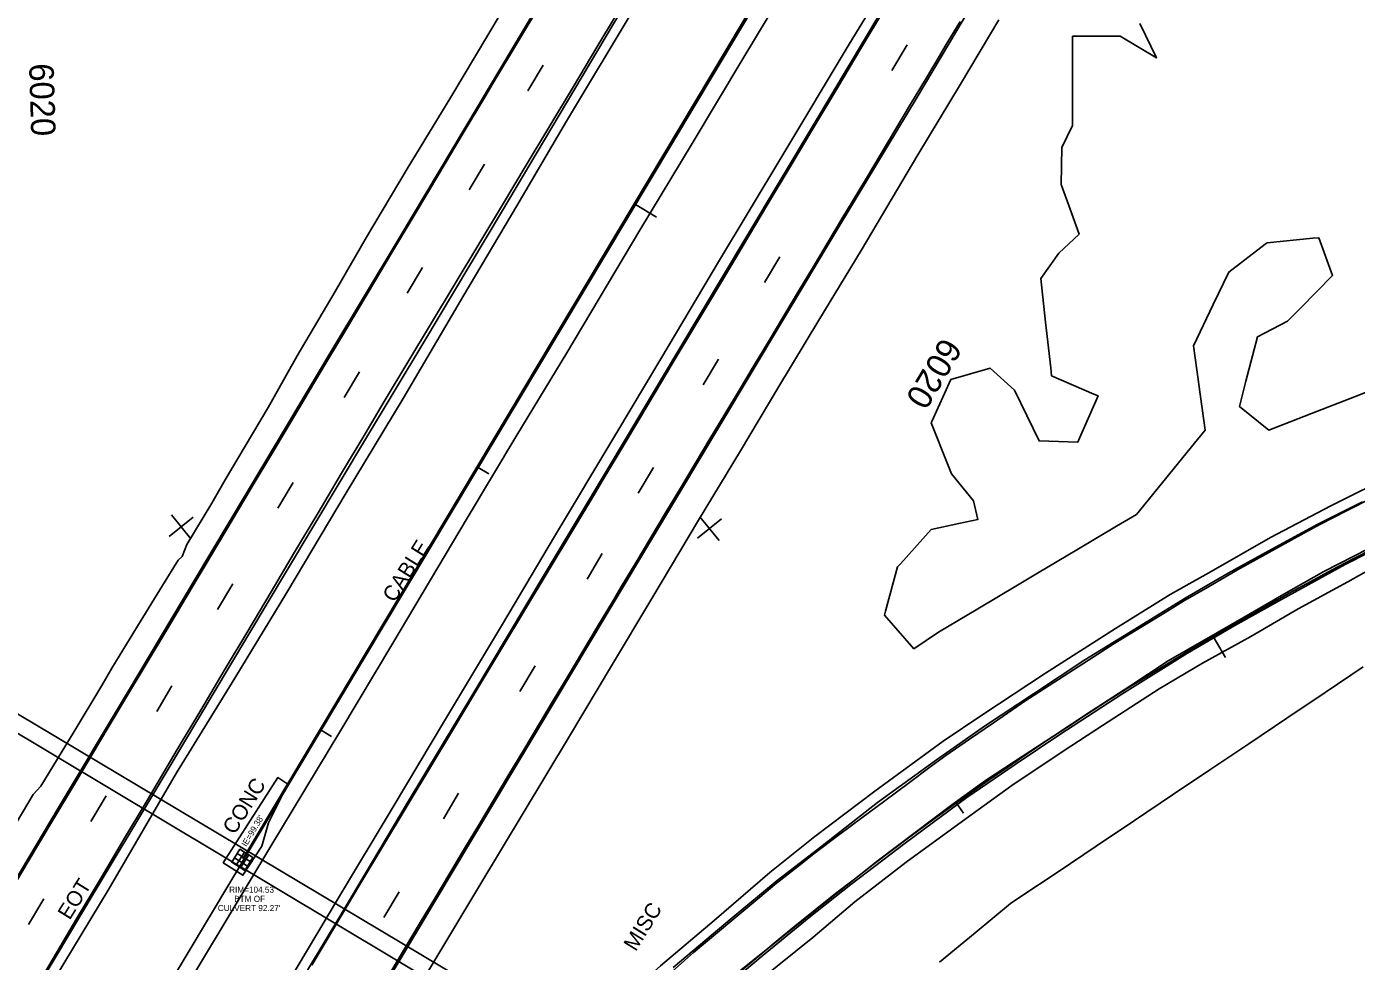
# Model space of a CAD drawing. Extents: x 2132221 to 2141942, y 535736 to 547298.
# Drawn here: x 2137298 to 2137732.2, y 539432.5 to 539737.8 of the extents above; entities that cross this region are included whole.
import ezdxf

# ---------------------------------------------------------------- set-up
doc = ezdxf.new("R2010")
doc.units = 0
for name, color, linetype in [('RD_EX_Conc', 7, 'Continuous'), ('RD_EX_Conc_txCode', 7, 'Continuous'), ('RD_EX_DR_Inlet', 7, 'Continuous'), ('RD_EX_DR_Inlet_txCode', 7, 'Continuous'), ('RD_EX_DR_Pipe', 7, 'Continuous'), ('RD_EX_GuardRail', 7, 'Continuous'), ('RD_EX_GuardRail_txCode', 7, 'Continuous'), ('RD_EX_Misc', 7, 'Continuous'), ('RD_EX_Misc_txCode', 7, 'Continuous'), ('RD_EX_Road', 7, 'Continuous'), ('RD_EX_VEG', 7, 'Continuous'), ('RD_HC_Cl', 7, 'Continuous'), ('RD_HC_Data_Tic', 7, 'Continuous'), ('RD_HC_TX_Sta50', 7, 'Continuous')]:
    doc.layers.add(name, color=color, linetype=linetype)

msp = doc.modelspace()

# ---------------------------------------------------------------- linework, layer by layer
at = {"layer": 'RD_EX_Conc'}
for p, q in [((2137527.69, 539374.58), (2137173.5, 539585.79)), ((2137170.3, 539581.57), (2137523.27, 539370.49))]:
    msp.add_line(p, q, dxfattribs=at)
for points in [[(2137242.23, 539372.03), (2137263.99, 539408.38), (2137286.63, 539446.29), (2137308.35, 539482.58), (2137330.9, 539520.32), (2137352.84, 539557.03), (2137375.41, 539594.83), (2137397.01, 539631.04), (2137419.62, 539668.7), (2137441.46, 539705.12), (2137463.96, 539742.92), (2137485.77, 539779.43), (2137508.5, 539817.41), (2137530.04, 539853.47), (2137547.89, 539883.34), (2137565.16, 539912.21), (2137584.16, 539944.01), (2137609.52, 539986.34), (2137628.42, 540017.94)], [(2137263.04, 539359.5), (2137275.58, 539380.34), (2137294.64, 539412.29), (2137320.12, 539454.95), (2137338.88, 539486.39), (2137364.26, 539528.76), (2137383.24, 539560.45), (2137408.68, 539602.98), (2137427.67, 539634.75), (2137453.05, 539677.2), (2137471.87, 539708.82), (2137497.19, 539751.42), (2137516.41, 539783.43), (2137541.62, 539825.46), (2137561.12, 539858.06), (2137585.95, 539899.61), (2137605.04, 539931.67), (2137630.62, 539974.42), (2137649.49, 540005.97)], [(2137333.67, 539335.96), (2137355.29, 539372.23), (2137365.06, 539388.65), (2137377.92, 539410.12), (2137399.62, 539446.12), (2137422.3, 539484.15), (2137444, 539520.34), (2137466.68, 539558.23), (2137488.53, 539594.68), (2137510.97, 539632.25), (2137532.88, 539668.78), (2137555.26, 539706.26), (2137576.91, 539742.44), (2137599.85, 539780.45), (2137621.54, 539816.61), (2137644.15, 539854.85), (2137665.88, 539890.9), (2137688.75, 539929.11), (2137713.64, 539970.82)], [(2137730.9, 539952.54), (2137709.36, 539916.37), (2137691.52, 539886.57), (2137674.64, 539858.53), (2137661.7, 539836.86), (2137649.76, 539817.01), (2137632.95, 539788.69), (2137616.77, 539761.89), (2137588.72, 539714.71), (2137563.22, 539672.35), (2137544.53, 539641.12), (2137524.37, 539607.53), (2137505.33, 539575.66), (2137487.21, 539545.55), (2137464.95, 539508.2), (2137442.94, 539471.57), (2137420.66, 539434.19), (2137398.45, 539397.12), (2137376.07, 539359.84), (2137349.68, 539315.66)], [(2137734.17, 539582.61), (2137719.58, 539575.27), (2137703.41, 539566.47), (2137690.33, 539559.31), (2137676.29, 539551.11), (2137659.32, 539540.7), (2137643.55, 539531.01), (2137626.75, 539519.85), (2137611.11, 539509.53), (2137595.1, 539498.32), (2137575.83, 539484.34), (2137557.23, 539469.83), (2137543.04, 539458.88), (2137528.33, 539446.78), (2137509.12, 539430.53)], [(2137750.62, 539573.33), (2137728.53, 539562.07), (2137707.69, 539550.71), (2137692.5, 539542.14), (2137677.03, 539533.19), (2137655.6, 539519.79), (2137635.4, 539506.63), (2137620.8, 539496.82), (2137605.04, 539485.98), (2137585.32, 539471.48), (2137567.1, 539457.65), (2137553.56, 539446.85), (2137538.45, 539434.49), (2137519.49, 539418.57), (2137502.42, 539403.19), (2137489.14, 539390.68), (2137475.58, 539377.67), (2137458.33, 539360.72), (2137441.76, 539343.31), (2137429.79, 539330.42), (2137417.48, 539316.71), (2137401.29, 539297.54), (2137386.22, 539279.28)]]:
    msp.add_lwpolyline(points, dxfattribs=at)
msp.add_lwpolyline([(2137374.8, 539470.14), (2137368.65, 539460.62), (2137362.2, 539464.71), (2137380, 539492.5), (2137383.28, 539490.34), (2137377.04, 539477.73)], close=True, dxfattribs=at)
at = {"layer": 'RD_EX_DR_Inlet'}
for p, q in [((2137366.42, 539463.98), (2137369.1, 539468.2)), ((2137366.81, 539467.76), (2137371.03, 539465.08)), ((2137365.9, 539466.33), (2137370.12, 539463.65)), ((2137367.85, 539463.07), (2137370.53, 539467.29))]:
    msp.add_line(p, q, dxfattribs=at)
msp.add_lwpolyline([(2137369.21, 539462.21), (2137364.98, 539464.89), (2137367.66, 539469.11), (2137371.88, 539466.43)], close=True, dxfattribs=at)
at = {"layer": 'RD_EX_DR_Pipe'}
msp.add_line((2137703.6, 540026.84), (2137368.64, 539465.96), dxfattribs=at)
at = {"layer": 'RD_EX_GuardRail'}
msp.add_lwpolyline([(2137592.36, 539832.15), (2137568.26, 539787.9), (2137548.04, 539754.27), (2137531.87, 539727.26), (2137515.31, 539699.54), (2137498.28, 539671.31), (2137474.37, 539631.17), (2137458.05, 539604.34), (2137441.86, 539577.27), (2137417.6, 539536.44), (2137400.33, 539507.43), (2137377.39, 539469.62), (2137353.17, 539429.19), (2137317.32, 539368.74), (2137297.36, 539335.79)], dxfattribs=at)
at = {"layer": 'RD_EX_Misc'}
for p, q in [((2137580.49, 539723.41), (2137585.48, 539731.8)), ((2137461.7, 539716.8), (2137466.7, 539725.18)), ((2137442.51, 539684.45), (2137447.5, 539692.84)), ((2137422.23, 539650.68), (2137427.22, 539659.06)), ((2137538.96, 539654.24), (2137543.96, 539662.62)), ((2137518.95, 539620.81), (2137523.94, 539629.19)), ((2137401.7, 539616.65), (2137406.7, 539625.03)), ((2137497.73, 539585.35), (2137502.72, 539593.74)), ((2137380.08, 539580.5), (2137385.08, 539588.89)), ((2137344.59, 539571.24), (2137352.36, 539577.53)), ((2137345.33, 539578.27), (2137351.62, 539570.5)), ((2137517.08, 539570.68), (2137524.85, 539576.97)), ((2137517.82, 539577.71), (2137524.11, 539569.94)), ((2137480.99, 539557.34), (2137485.98, 539565.72)), ((2137360.33, 539547.39), (2137365.32, 539555.78)), ((2137459.05, 539520.63), (2137464.05, 539529.02)), ((2137340.49, 539514.09), (2137345.48, 539522.48)), ((2137319.02, 539478.18), (2137324.02, 539486.56)), ((2137434.07, 539479.01), (2137439.06, 539487.4)), ((2137414.63, 539446.82), (2137419.62, 539455.21)), ((2137298.66, 539444.5), (2137303.65, 539452.89))]:
    msp.add_line(p, q, dxfattribs=at)
for points in [[(2137465.66, 539744.9), (2137457.97, 539732.02), (2137450.27, 539719.14), (2137447.96, 539715.27), (2137440.27, 539702.39), (2137432.58, 539689.52), (2137424.89, 539676.64), (2137417.19, 539663.76), (2137409.5, 539650.88), (2137401.81, 539638.01), (2137394.12, 539625.13), (2137386.43, 539612.25), (2137378.73, 539599.37), (2137371.04, 539586.5), (2137363.35, 539573.62), (2137355.66, 539560.74), (2137352.41, 539555.3), (2137344.72, 539542.43), (2137337.03, 539529.55), (2137329.33, 539516.67), (2137321.64, 539503.79), (2137313.95, 539490.92), (2137306.26, 539478.04), (2137298.57, 539465.16), (2137290.87, 539452.28)], [(2137490.31, 539741.19), (2137484.23, 539731.06), (2137476.52, 539718.19), (2137468.8, 539705.33), (2137461.09, 539692.46), (2137453.37, 539679.6), (2137445.66, 539666.74), (2137437.95, 539653.87), (2137430.23, 539641.01), (2137422.52, 539628.14), (2137414.8, 539615.28), (2137408.52, 539604.8), (2137400.86, 539591.91), (2137393.19, 539579.02), (2137385.53, 539566.12), (2137377.86, 539553.23), (2137370.2, 539540.33), (2137362.54, 539527.44), (2137354.87, 539514.55), (2137347.21, 539501.65), (2137345, 539497.95), (2137337.34, 539485.05), (2137329.67, 539472.16), (2137322.01, 539459.26), (2137314.35, 539446.37), (2137306.68, 539433.48), (2137299.02, 539420.58)], [(2137578.12, 539743.48), (2137570.42, 539730.61), (2137562.72, 539717.74), (2137555.02, 539704.86), (2137547.32, 539691.99), (2137539.62, 539679.12), (2137531.92, 539666.25), (2137524.22, 539653.37), (2137516.52, 539640.5), (2137508.82, 539627.63), (2137501.12, 539614.75), (2137493.43, 539601.88), (2137485.73, 539589.01), (2137483.72, 539585.65), (2137476, 539572.79), (2137468.28, 539559.93), (2137460.56, 539547.07), (2137452.84, 539534.21), (2137445.12, 539521.35), (2137437.4, 539508.49), (2137429.69, 539495.63), (2137421.97, 539482.76), (2137414.25, 539469.9), (2137406.53, 539457.04), (2137398.81, 539444.18), (2137391.09, 539431.32)], [(2137602.78, 539739.37), (2137597.95, 539731.32), (2137596.3, 539728.55), (2137591.47, 539720.5), (2137586.65, 539712.45), (2137581.83, 539704.4), (2137577, 539696.35), (2137572.18, 539688.3), (2137569.37, 539683.6), (2137564.54, 539675.55), (2137559.72, 539667.5), (2137554.89, 539659.45), (2137550.07, 539651.4), (2137545.25, 539643.35), (2137540.42, 539635.29), (2137535.6, 539627.24), (2137530.77, 539619.19), (2137525.95, 539611.14), (2137521.13, 539603.09), (2137516.3, 539595.04), (2137511.48, 539586.98), (2137506.65, 539578.93), (2137501.83, 539570.88), (2137497.01, 539562.83), (2137492.18, 539554.78), (2137489.25, 539549.89), (2137484.43, 539541.83), (2137479.6, 539533.78), (2137474.78, 539525.73), (2137469.95, 539517.68), (2137465.13, 539509.63), (2137460.31, 539501.58), (2137455.48, 539493.52), (2137450.66, 539485.47), (2137445.83, 539477.42), (2137441.01, 539469.37), (2137436.19, 539461.32), (2137431.36, 539453.27), (2137426.54, 539445.21), (2137421.71, 539437.16), (2137416.89, 539429.11)], [(2137505.79, 539426.6), (2137512.85, 539432.85), (2137515.7, 539435.38), (2137522.94, 539441.42), (2137530.18, 539447.45), (2137537.42, 539453.49), (2137542.32, 539457.57), (2137549.71, 539463.42), (2137555.57, 539468.05), (2137563.13, 539473.69), (2137570.7, 539479.33), (2137578.26, 539484.96), (2137585.82, 539490.6), (2137593.39, 539496.24), (2137598.1, 539499.75), (2137605.88, 539505.09), (2137613.66, 539510.44), (2137621.44, 539515.78), (2137623.96, 539517.52), (2137631.9, 539522.64), (2137639.83, 539527.76), (2137647.76, 539532.88), (2137652.74, 539536.09), (2137660.8, 539541.01), (2137668.86, 539545.93), (2137676.92, 539550.85), (2137677.03, 539550.92), (2137685.22, 539555.61), (2137693.41, 539560.31), (2137698.45, 539563.2), (2137706.73, 539567.75), (2137715.01, 539572.29), (2137720.49, 539575.31), (2137728.9, 539579.61), (2137737.31, 539583.92)], [(2137744.73, 539571.65), (2137731.36, 539564.85), (2137721.53, 539559.86), (2137708.53, 539552.38), (2137695.53, 539544.9), (2137682.52, 539537.42), (2137670.7, 539530.63), (2137658.16, 539522.41), (2137645.61, 539514.2), (2137633.06, 539505.98), (2137620.51, 539497.76), (2137611.12, 539491.62), (2137600.13, 539483.6), (2137588.14, 539474.59), (2137576.15, 539465.57), (2137575.13, 539464.81), (2137563.42, 539455.43), (2137551.71, 539446.06), (2137540, 539436.69), (2137530.77, 539429.31)]]:
    msp.add_lwpolyline(points, dxfattribs=at)
at = {"layer": 'RD_EX_Road'}
for points in [[(2137262.82, 539351.95), (2137281.66, 539384.2), (2137304.23, 539421.92), (2137324.62, 539455.81), (2137346.95, 539494.12), (2137365.98, 539524.98), (2137382.97, 539552.95), (2137402.34, 539585.47), (2137421, 539616.32), (2137440.79, 539650.02), (2137458.12, 539679.26), (2137474.32, 539706.92), (2137495.73, 539742.57), (2137510.44, 539767.21), (2137528.18, 539796.71), (2137547.34, 539828.56), (2137566.47, 539860.5), (2137583.1, 539889.05), (2137601.67, 539919.51), (2137620.06, 539950.89), (2137640.86, 539984.68), (2137653.2, 540005.1)], [(2137324.83, 539328.87), (2137342.23, 539357.26), (2137362.06, 539390.06), (2137382.99, 539425.01), (2137399.53, 539452.71), (2137417.7, 539482.98), (2137434.42, 539511.01), (2137453.36, 539542.64), (2137470.34, 539571.3), (2137490.4, 539604.67), (2137505.05, 539629.27), (2137523.94, 539660.93), (2137544.6, 539695.33), (2137566.61, 539732.02), (2137588.55, 539768.02), (2137611.63, 539807.13), (2137631.63, 539840.98), (2137648.48, 539868.92), (2137668.45, 539902.66), (2137688.62, 539936.21), (2137708.24, 539968.78)], [(2137231.11, 539371.27), (2137249.17, 539401.42), (2137272.6, 539440.72), (2137300.11, 539487.03), (2137302.61, 539489.71), (2137313.58, 539507.61), (2137322.6, 539522.56), (2137325.81, 539528.24), (2137334.23, 539541.92), (2137342.34, 539555.22), (2137347.46, 539563.53), (2137348.75, 539564.77), (2137350.27, 539568.62), (2137358.47, 539582.13), (2137362.81, 539589.77), (2137369.41, 539600.76), (2137376.87, 539613.41), (2137386.34, 539630.25), (2137398.78, 539651.22), (2137408.93, 539668.96), (2137422.27, 539691.25), (2137436.48, 539714.76), (2137452.6, 539741.72)], [(2137356.91, 539308.32), (2137369.5, 539329.65), (2137384.59, 539353.73), (2137397.29, 539376.03), (2137408.9, 539395.48), (2137420.85, 539415.41), (2137430.98, 539432.35), (2137445.95, 539457.39), (2137460.1, 539480.86), (2137475.28, 539506), (2137488.98, 539529.07), (2137502.16, 539551.03), (2137517.42, 539576.6), (2137531.09, 539599.17), (2137543.64, 539620.2), (2137556.68, 539641.88), (2137570.47, 539664.65), (2137589.03, 539695.92), (2137602.93, 539718.99), (2137615.45, 539739.96)], [(2137745.3, 539591.9), (2137723.8, 539581.28), (2137704.12, 539570.87), (2137684.77, 539559.86), (2137671.4, 539552.35), (2137653.49, 539541.21), (2137630.71, 539526.66), (2137610.19, 539513.1), (2137597.26, 539504.44), (2137574.94, 539488.13), (2137555.4, 539473.33), (2137540.71, 539461.53), (2137522.48, 539445.87), (2137504.99, 539431.11), (2137489.61, 539417.35), (2137474.28, 539403.35), (2137462.64, 539392.07), (2137445.1, 539374.65), (2137428.62, 539358.35), (2137417.89, 539345.97), (2137403.86, 539330.21), (2137388.16, 539312.34), (2137371.7, 539292.54)], [(2137742.38, 539563.73), (2137729.35, 539556.45), (2137713.2, 539547.68), (2137697.67, 539538.57), (2137681.95, 539529.85), (2137667.82, 539521.51), (2137649.27, 539509.52), (2137636.42, 539501.18), (2137619.68, 539489.93), (2137604.72, 539479.15), (2137585.17, 539464.87), (2137568.39, 539451.94), (2137554.7, 539440.32), (2137537.52, 539426.48), (2137516.7, 539408.79), (2137499.32, 539392.72), (2137478.91, 539373.82), (2137461.2, 539356.32), (2137445.38, 539339.73), (2137429.48, 539322.89), (2137408.9, 539299.43), (2137390.6, 539276.98)]]:
    msp.add_lwpolyline(points, dxfattribs=at)
at = {"layer": 'RD_EX_VEG'}
for points in [[(2137661.47, 539738.72), (2137666.9, 539727.52), (2137655.06, 539734.6), (2137640.06, 539734.6), (2137639.5, 539734.6), (2137639.5, 539719.6), (2137639.5, 539717.19), (2137639.5, 539705.43), (2137635.99, 539698.26), (2137635.83, 539686.19), (2137638.73, 539678.1), (2137641.63, 539670.01), (2137635.07, 539663.75), (2137629.12, 539655.5), (2137630.72, 539641.19), (2137632.39, 539626.29), (2137632.68, 539623.75), (2137646.43, 539617.75), (2137647.82, 539617.14), (2137641.82, 539603.39), (2137641.21, 539602.01), (2137628.59, 539602.45), (2137624.58, 539610.73), (2137620.57, 539619.01), (2137612.56, 539626.23), (2137599.74, 539622.49), (2137593.55, 539608.82), (2137593.33, 539608.32), (2137598.94, 539594.41), (2137600.01, 539591.76), (2137607.22, 539582.94), (2137608.55, 539576.79), (2137602.41, 539575.46), (2137593.33, 539573.48), (2137583.3, 539562.32), (2137582.38, 539561.29), (2137578.45, 539546.82), (2137578.1, 539545.53), (2137587.72, 539534.57), (2137595.74, 539540), (2137608.63, 539547.67), (2137621.52, 539555.34), (2137628.06, 539559.24), (2137640.95, 539566.91), (2137653.84, 539574.58), (2137660.38, 539578.48), (2137669.84, 539590.12), (2137679.3, 539601.76), (2137682.75, 539606), (2137680.73, 539620.86), (2137680.61, 539621.77), (2137679.02, 539633.47), (2137685.47, 539647.01), (2137690.49, 539657.57), (2137702.4, 539666.7), (2137703.04, 539667.19), (2137717.98, 539668.62), (2137719.87, 539668.8), (2137724.41, 539656.5), (2137713.9, 539645.8), (2137709.72, 539641.54), (2137699.84, 539636.46), (2137696.08, 539621.94), (2137693.96, 539613.75), (2137703.58, 539606), (2137717.55, 539611.45), (2137731.53, 539616.9), (2137735.1, 539618.29)], [(2137734.42, 539528.69), (2137721.97, 539520.32), (2137709.52, 539511.96), (2137697.06, 539503.6), (2137684.61, 539495.24), (2137672.16, 539486.88), (2137659.7, 539478.52), (2137647.25, 539470.16), (2137634.79, 539461.8), (2137622.34, 539453.44), (2137619.25, 539451.36), (2137607.68, 539441.82), (2137596.1, 539432.27)]]:
    msp.add_lwpolyline(points, dxfattribs=at)
at = {"layer": 'RD_HC_Cl'}
msp.add_line((2139719.79, 543396.28), (2136851.48, 538600.7), dxfattribs=at)
msp.add_arc((2138238.15, 538594.85), 1093.7, 40.39109, 144.99812, dxfattribs=at)
at = {"layer": 'RD_HC_Data_Tic'}
for p, q in [((2137496.79, 539679.61), (2137503.66, 539675.5)), ((2137445.46, 539593.79), (2137448.9, 539591.73)), ((2137685.44, 539538.61), (2137689.48, 539531.71)), ((2137394.13, 539507.97), (2137397.56, 539505.91)), ((2137601.58, 539484.2), (2137603.91, 539480.95))]:
    msp.add_line(p, q, dxfattribs=at)

# ---------------------------------------------------------------- texts
at = {"layer": 'RD_EX_Conc_txCode'}
msp.add_text('CONC', height=5, rotation=58.1344, dxfattribs=at).set_placement((2137365.92, 539473.62))
at = {"layer": 'RD_EX_DR_Inlet_txCode'}
msp.add_text("IE=99.38'", height=2, rotation=59.1539, dxfattribs=at).set_placement((2137369.77, 539469.8))
for s, p in [("RIM=104.53'", (2137364.14, 539454.93)), ("CULVERT 92.27'", (2137360.44, 539448.93)), ('BTM OF', (2137365.78, 539451.93))]:
    msp.add_text(s, height=2, dxfattribs=at).set_placement(p)
at = {"layer": 'RD_EX_GuardRail_txCode'}
msp.add_text('CABLE', height=5, rotation=58.014, dxfattribs=at).set_placement((2137418.13, 539549.43))
at = {"layer": 'RD_EX_Misc_txCode'}
for s, p in [('EOT', (2137312.07, 539445.76)), (' MISC', (2137495.88, 539433.94))]:
    msp.add_text(s, height=5, rotation=58.1344, dxfattribs=at).set_placement(p)
at = {"layer": 'RD_HC_TX_Sta50'}
for rotation, p in [(271.6792, (2137298.82, 539725.65)), (271.6792, (2137298.82, 539725.65)), (239.1157, (2137596.98, 539636.71))]:
    msp.add_text('6020', height=8, rotation=rotation, dxfattribs=at).set_placement(p)

doc.saveas('drawing.dxf')
